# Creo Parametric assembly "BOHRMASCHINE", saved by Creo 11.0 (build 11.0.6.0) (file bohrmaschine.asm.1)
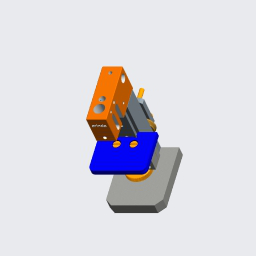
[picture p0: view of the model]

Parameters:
  ERSTELLER = "ARINDA"
  BENENNUNG = "XXX"
  TEILETYP = "K"

Other parameters: MASSE, TRANSLATION1_STATIC_FRICTION, TRANSLATION1_KINETIC_FRICTION, TRANSLATION1_RESTITUTION, TRANSLATION1_MINIMUM_LIMIT, TRANSLATION1_MAXIMUM_LIMIT, TRANSLATION1_ZERO_POSITION, ROTATION1_STATIC_FRICTION, ROTATION1_KINETIC_FRICTION, ROTATION1_CONTACT_RADIUS, ROTATION1_RESTITUTION, ROTATION1_MINIMUM_LIMIT, ROTATION1_MAXIMUM_LIMIT, ROTATION1_ZERO_POSITION

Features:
  1. coordinate system
  2. datum plane "A_RECHTS_Y-Z"
  3. datum plane "A_OBEN_X-Z"
  4. datum plane "A_VORNE_X-Y"
  5. datum axis
  6. datum axis
  7. datum axis
  8. datum point "APNT0"
  9. component "BODENPLATTE"
  10. component "STÄNDER"
  11. component "DIN_912"
  12. component "GETRIEBEGEHÄUSE_ARINDA"
  13. component "FÜHRUNGSLEISTE"
  14. component "DIN913_45H"
  15. component "ISO4032_1"
  16. pattern
  17. component "ISO2338"
  18. component "ISO2338"
  19. component "DIN_912"
  20. component "RÄNDELSCHRAUBE"
  21. component "MASCHINENTISCH"
  22. component "ANTRIEBSSCHEIBE"
  23. component "ISO7435"
  24. component "ISO4032_1"
  25. component "ISO7090T1"
  26. component "KURBEL"
  27. component "ISO4032_1"
  28. component "ISO2338"
  29. component
  30. component
  31. component
  32. component
  33. component
  34. component "ISO7434_M4X4.PRT"
  35. component

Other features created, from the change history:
  planar section "XSEC0001"
  planar section "XSEC0002"
  feature "Motor 1"
  component "DIN7513M3BX6.PRT"
  component "RIEMEN.PRT"
  group "COPIED_GROUP"

Other named items: AA_X, AA_Y, AA_Z, ACS0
